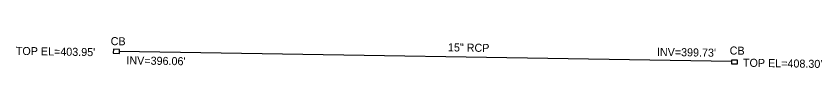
# Model space of a CAD drawing. Extents: x 1975859 to 1978323, y 778892 to 782836.
# Drawn here: x 1976615.6 to 1977016.9, y 780868.3 to 780883.8 of the extents above; entities that cross this region are included whole.
import ezdxf

# ---------------------------------------------------------------- set-up
doc = ezdxf.new("R2010")
doc.units = 0
for name, color, linetype in [('Exist Structure Minor Catch Basin', 7, 'Continuous'), ('Exist Structure Minor Catch Basin Text', 7, 'Continuous'), ('Exist Structure Minor Catch Basin Top Elevation', 7, 'Continuous'), ('Exist Structure Minor Pipes RCP 15 Inch', 7, 'Continuous'), ('Exist Structure Minor Pipes RCP 15 Inch Invert', 7, 'Continuous'), ('Exist Structure Minor Pipes RCP 15 Inch Text', 7, 'Continuous')]:
    doc.layers.add(name, color=color, linetype=linetype)

msp = doc.modelspace()

# ---------------------------------------------------------------- linework, layer by layer
at = {"layer": 'Exist Structure Minor Catch Basin'}
for p, q in [((1976667.1, 780875.62), (1976667.16, 780877.5)), ((1976974.85, 780870.39), (1976974.9, 780872.26))]:
    msp.add_line(p, q, dxfattribs=at)
for points in [[(1976667.16, 780877.5), (1976664.07, 780877.63), (1976664.01, 780875.7), (1976667.1, 780875.62)], [(1976974.9, 780872.26), (1976971.85, 780872.33), (1976971.81, 780870.47), (1976974.85, 780870.39)]]:
    msp.add_lwpolyline(points, dxfattribs=at)
at = {"layer": 'Exist Structure Minor Pipes RCP 15 Inch'}
msp.add_line((1976971.9, 780871.57), (1976667, 780876.6), dxfattribs=at)

# ---------------------------------------------------------------- texts
at = {"layer": 'Exist Structure Minor Catch Basin Text'}
for p in [(1976662.7, 780879.74), (1976970.93, 780875.06)]:
    msp.add_text('CB', height=4, rotation=359.0355, dxfattribs=at).set_placement(p)
at = {"layer": 'Exist Structure Minor Catch Basin Top Elevation'}
for s, p in [("TOP EL=403.95'", (1976615.47, 780874.88)), ("TOP EL=408.30'", (1976977.55, 780869.02))]:
    msp.add_text(s, height=4, rotation=359.0355, dxfattribs=at).set_placement(p)
at = {"layer": 'Exist Structure Minor Pipes RCP 15 Inch Invert'}
for s, p in [("INV=399.73'", (1976934.69, 780874.41)), ("INV=396.06'", (1976670.55, 780870.19))]:
    msp.add_text(s, height=4, rotation=359.0355, dxfattribs=at).set_placement(p)
at = {"layer": 'Exist Structure Minor Pipes RCP 15 Inch Text'}
msp.add_text('15" RCP', height=4, rotation=359.0542, dxfattribs=at).set_placement((1976830.66, 780876.65))

doc.saveas('drawing.dxf')
